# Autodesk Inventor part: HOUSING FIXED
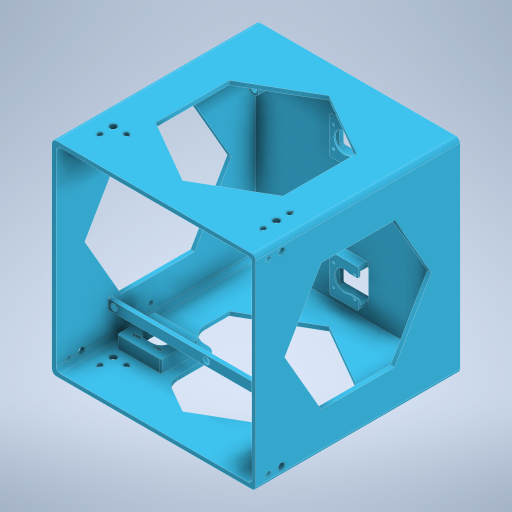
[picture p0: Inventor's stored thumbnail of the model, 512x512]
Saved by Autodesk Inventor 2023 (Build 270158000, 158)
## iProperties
Created: 2025-07
Part Number: HOUSING FIXED
Material: Generic
Document SubType Name: Modeling
Designer: erjon
Density: 1 g/cm^3
Appearance: Default
Author: erjon
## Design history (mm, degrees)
feature "Base1"
body "Solid1"
